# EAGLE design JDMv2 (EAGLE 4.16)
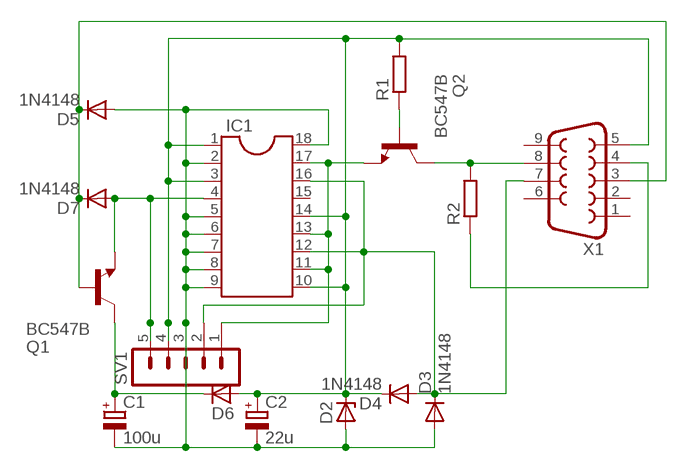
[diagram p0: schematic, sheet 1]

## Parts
C1  100u  CPOL-EUE2.5-6  [E2,5-6]
C2  22u  CPOL-EUE2.5-6  [E2,5-6]
D2  ZENER-DIODEDO35Z10  [DO35Z10]
D3  1N4148  [DO35-10]
D4  1N4148  [DO35-10]
D5  1N4148  [DO35-10]
D6  ZENER-DIODEDO35Z10  [DO35Z10]
D7  1N4148  [DO35-10]
IC1  DIL18S  [SOCKED-18]
Q1  BC547B  [TO92]
Q2  BC547B  [TO92]
R1  R-EU_0207/10  [0207/10]
R2  R-EU_0207/7  [0207/7]
SV1  MA05-1  [MA05-1]
X1  F09H  [F09H]

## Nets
N$1: Q2.3(C) R2.2 X1.8
N$2: R2.1 X1.4
N$3: Q2.2(B) R1.1
N$6: D3.C D4.A IC1.12 IC1.16 SV1.2 X1.7
N$7: C2.+ D2.C D4.C D6.A IC1.1 IC1.3 IC1.10 IC1.14 R1.2 SV1.4 X1.5
N$8: C1.+ D6.C Q1.3(C)
N$10: D5.C D7.C Q1.2(B) X1.3
N$11: D7.A IC1.4 Q1.1(E) SV1.5
N$12: C1.- C2.- D2.A D3.A D5.A IC1.2 IC1.5 IC1.6 IC1.7 IC1.8 IC1.9 IC1.18 SV1.3
N$13: IC1.11 IC1.13 IC1.17 Q2.1(E) SV1.1
Unconnected: IC1.15 X1.1 X1.2 X1.6 X1.9

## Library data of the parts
C1 C2 = rcl:CPOL-EU: POLARIZED CAPACITOR, European symbol
D2 D6 = diode:ZENER-DIODE: Z-Diode
D3-D5 D7 = diode:1N4148: DIODE
IC1 = ic-package:DIL18: Dual In Line
Q1 Q2 = transistor-npn:BC547*: NPN Transistor
R1 R2 = rcl:R-EU_: RESISTOR, European symbol
SV1 = con-lstb:MA05-1: PIN HEADER
X1 = con-subd:F09: SUB-D

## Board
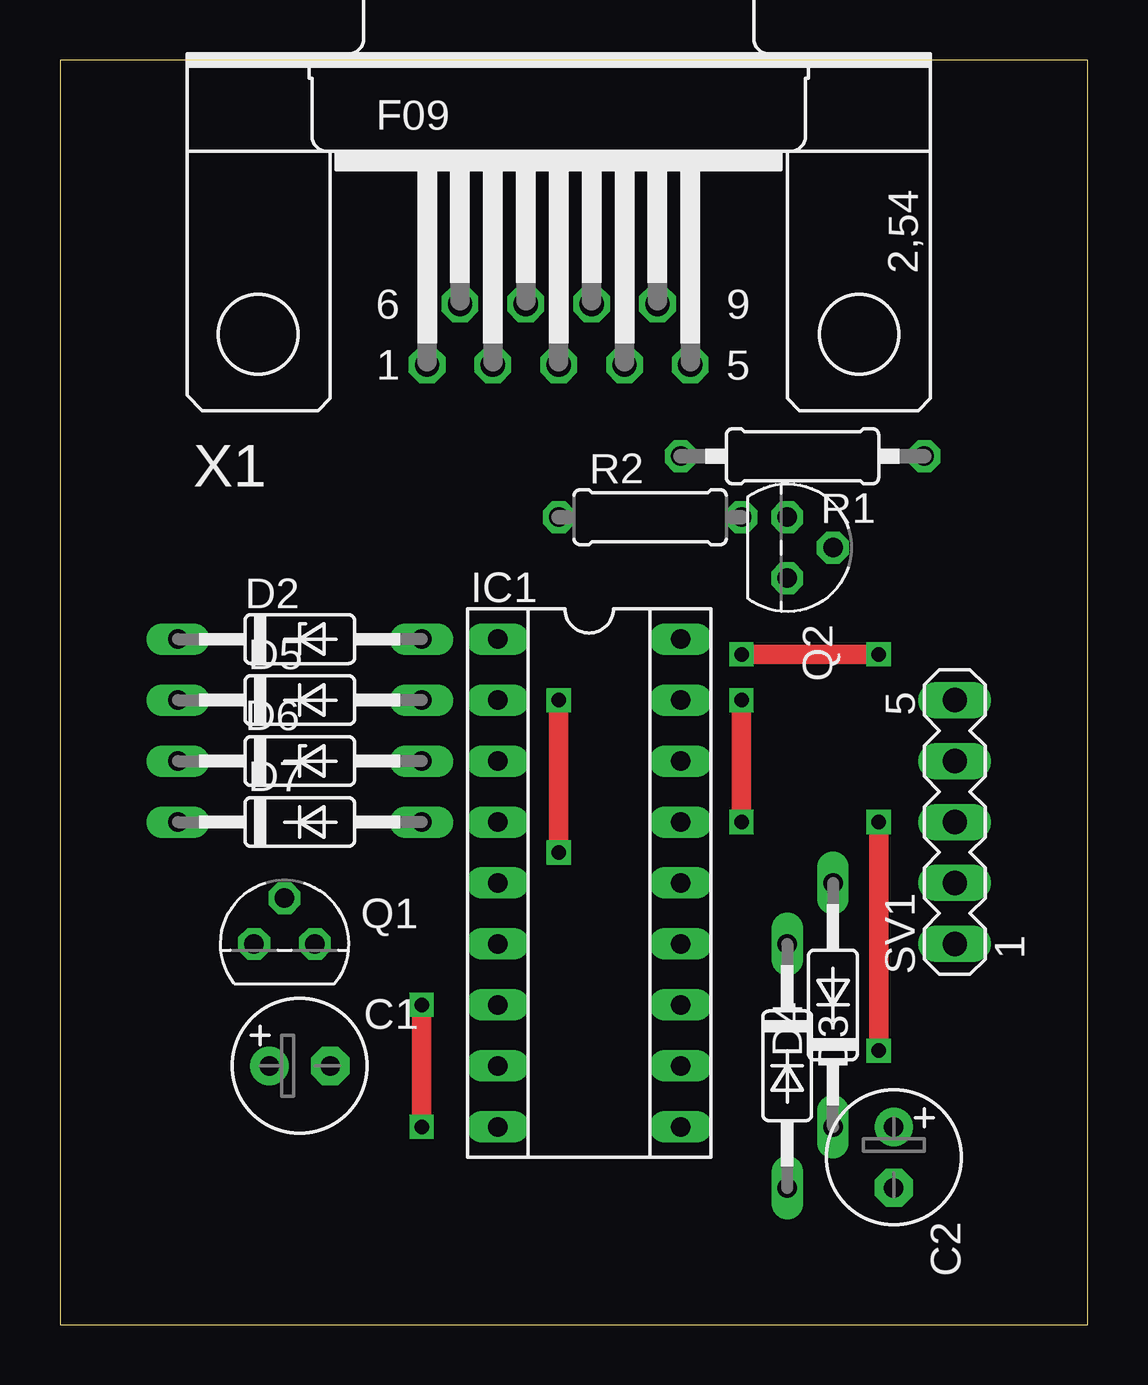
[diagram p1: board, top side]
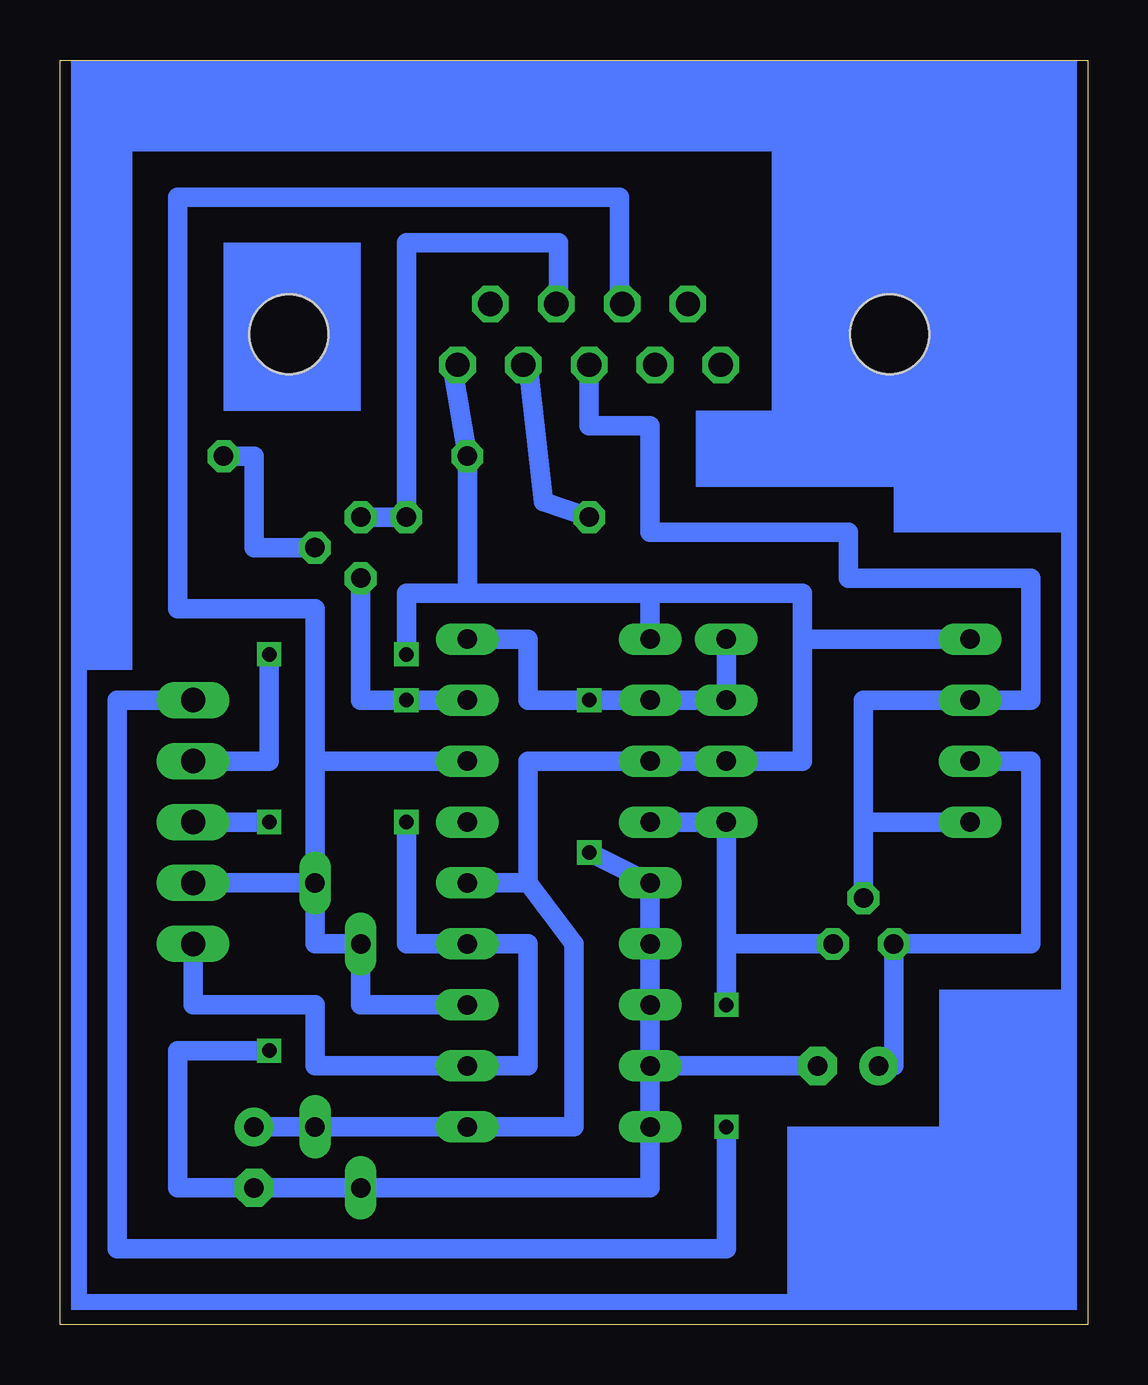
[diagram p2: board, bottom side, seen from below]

Size 42.85 x 52.7 mm. Coordinates in mm from the lower left corner, seen from the top.
Outline: 0,0 42.85,0 42.85,52.7 0,52.7 0,0
Copper layers (1*16): Top 0.035mm / dielectric 1.5mm / Bottom 0.035mm
Design rules "default": minimum track width 10mil, minimum drill 24mil, track to track 8mil, track to pad 8mil, pad to pad 8mil, via to via 8mil, smd to smd 8mil, copper to edge 40mil, drill to drill 8mil, minimum pad ring 10mil, minimum via ring 8mil, stop-mask expansion 4mil, vias tented up to drill 0mil, thermal gap 10mil

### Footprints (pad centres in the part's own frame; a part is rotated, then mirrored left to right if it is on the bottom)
E2,5-6 = drill 0.813 pad 1.6 round: + -1.27,0 | drill 0.813 pad 1.6 octagon: - 1.27,0
DO35Z10 = drill 0.813 long: A 5.08,0; C -5.08,0
DO35-10 = drill 0.813 long: A 5.08,0; C -5.08,0
SOCKED-18 = drill 0.813 long: 1 -10.16,-3.81; 2 -7.62,-3.81; 3 -5.08,-3.81; 4 -2.54,-3.81; 5 0,-3.81; 6 2.54,-3.81; 7 5.08,-3.81; 8 7.62,-3.81; 9 10.16,-3.81; 10 10.16,3.81; 11 7.62,3.81; 12 5.08,3.81; 13 2.54,3.81; 14 0,3.81; 15 -2.54,3.81; 16 -5.08,3.81; 17 -7.62,3.81; 18 -10.16,3.81
TO92 = drill 0.813 octagon: 1 1.27,0; 2 0,1.905; 3 -1.27,0
0207/10 = drill 0.813 octagon: 1 -5.08,0; 2 5.08,0
0207/7 = drill 0.813 octagon: 1 -3.81,0; 2 3.81,0
MA05-1 = drill 1.016 long: 1 -5.08,0; 2 -2.54,0; 3 0,0; 4 2.54,0; 5 5.08,0
F09H = drill 1.016 octagon: 1 -5.486,-1.27; 2 -2.743,-1.27; 3 0,-1.27; 4 2.743,-1.27; 5 5.486,-1.27; 6 -4.115,1.27; 7 -1.372,1.27; 8 1.372,1.27; 9 4.115,1.27 | hole 3.302: -12.522,0; 12.522,0

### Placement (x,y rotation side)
C1  10,10.79 0 top
C2  34.76,6.98 270 top
D2  10,28.57 0 top
D3  30.32,10.79 270 top
D4  32.22,13.33 90 top
D5  10,26.03 0 top
D6  10,23.49 0 top
D7  10,20.95 0 top
IC1  22.06,18.41 270 top
Q1  9.36,15.87 0 top
Q2  30.32,32.38 270 top
R1  30.95,36.19 180 top
R2  24.6,33.65 0 top
SV1  37.3,20.95 90 top
X1  20.79,41.27 0 top

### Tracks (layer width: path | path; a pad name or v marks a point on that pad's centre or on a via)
N$1
  Bottom 0.813: X1.8 22.06,42.54 22.06,45.08 28.41,45.08 R2.2 Q2.3
N$2
  Bottom 0.813: R2.1 22.7,34.29 23.33,40 X1.4
N$3
  Bottom 0.813: R1.1 34.76,36.19 34.76,32.38 Q2.2
N$6
  Bottom 0.813: X1.7 19.52,42.54 19.52,46.99 37.94,46.99 37.94,29.84 32.22,29.84 32.22,23.49 | 32.22,23.49 IC1.16 | D4.A SV1.2 | IC1.12 30.32,13.33 D3.C 32.22,15.87 D4.A | D4.A 32.22,23.49
N$7  (via drill 0.6)
  Top 0.813: v28.41,27.94 v34.12,27.94
  Bottom 0.813: 23.33,18.41 21.43,15.87 21.43,8.25 IC1.10 D4.C C2.+ | 23.33,18.41 IC1.14 | 23.33,18.41 23.33,23.49 IC1.3 D6.A 11.9,23.49 11.9,28.57 | X1.5 26.51,40 R1.2 25.87,30.48 | 18.25,30.48 25.87,30.48 | 11.9,28.57 D2.C | 18.25,30.48 IC1.1 | 18.25,30.48 11.9,30.48 11.9,28.57 | 25.87,30.48 28.41,30.48 v28.41,27.94 | v34.12,27.94 34.12,23.49 SV1.4
N$8
  Bottom 0.813: D6.C 2.38,23.49 2.38,15.87 Q1.3 8.09,10.79 C1.+
N$10
  Bottom 0.813: X1.3 20.79,37.46 18.25,37.46 18.25,33.02 10,33.02 10,31.11 2.38,31.11 2.38,26.03 D5.C 9.36,26.03 9.36,20.95 | 9.36,20.95 Q1.2 | D7.C 9.36,20.95
N$11  (via drill 0.6)
  Top 0.813: v15.08,8.25 v15.08,13.33
  Bottom 0.813: 15.08,15.87 Q1.1 | IC1.4 D7.A 15.08,15.87 | v15.08,8.25 15.08,3.17 40.48,3.17 40.48,26.03 SV1.5 | v15.08,13.33 15.08,15.87
N$12  (via drill 0.6)
  Top 0.813: v20.79,19.68 v20.79,26.03 | v34.12,11.43 v34.12,20.95
  Bottom 0.813: IC1.18 23.33,28.57 23.33,26.03 v20.79,26.03 IC1.2 D5.A D2.A | IC1.8 IC1.9 18.25,5.71 D3.A 33.49,5.71 | IC1.8 IC1.7 IC1.6 IC1.5 v20.79,19.68 | C1.- IC1.8 | 33.49,5.71 C2.- | v34.12,20.95 SV1.3 | 33.49,5.71 37.94,5.71 37.94,11.43 v34.12,11.43
N$13  (via drill 0.6)
  Top 0.813: v28.41,20.95 v28.41,26.03
  Bottom 0.813: IC1.17 v28.41,26.03 30.32,26.03 Q2.1 | SV1.1 37.3,13.33 32.22,13.33 32.22,10.79 IC1.11 23.33,10.79 23.33,15.87 IC1.13 28.41,15.87 v28.41,20.95
(copper drawn outside any net)
  shapes: Bottom area x12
